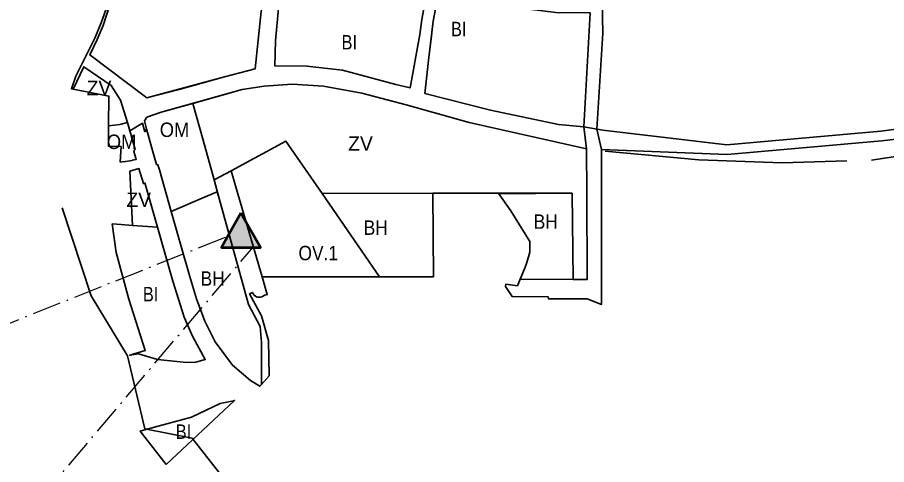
# Model space of a CAD drawing. Extents: x -650276 to -642489, y -1074311 to -1066658.
# Drawn here: x -645941 to -645218, y -1070271 to -1069899 of the extents above; entities that cross this region are included whole.
import ezdxf

# ---------------------------------------------------------------- set-up
doc = ezdxf.new("R2010")
doc.units = 0
doc.header["$LTSCALE"] = 4.8
doc.linetypes.add('DOT_DASHED', pattern=[7.7, 5, -1.2, 0.3, -1.2])
for name, color, linetype, lineweight in [('1', 7, 'Continuous', 35), ('11', 7, 'Continuous', 35), ('12', 7, 'Continuous', 35), ('15', 7, 'Continuous', 35), ('2', 7, 'Continuous', 35), ('40', 7, 'Continuous', 35), ('54', 7, 'Continuous', 35), ('55', 7, 'Continuous', 53)]:
    doc.layers.add(name, color=color, linetype=linetype, lineweight=lineweight)
doc.layers.add('62', color=7, linetype='Continuous')

msp = doc.modelspace()

# ---------------------------------------------------------------- hatches: boundary and pattern name
at = {"layer": '55'}
msp.add_hatch(color=256, dxfattribs=at).paths.add_polyline_path([(-645754.857, -1070061.969), (-645770.808, -1070090.615), (-645738.424, -1070090.615)])

# ---------------------------------------------------------------- linework, layer by layer
at = {"layer": '1'}
for points in [[(-645772.853, -1070049.868), (-645774.423, -1070044.167), (-645783.063, -1070047.855), (-645812.76, -1070060.53)], [(-645737.756, -1070204.389), (-645737.624, -1070169.544), (-645738.79, -1070156.281), (-645748.62, -1070137.889), (-645772.853, -1070049.868)], [(-645812.76, -1070060.53), (-645804.52, -1070089.63), (-645797.66, -1070113.88), (-645791.72, -1070133.09), (-645784.83, -1070151.9), (-645784.83, -1070151.9)], [(-645784.83, -1070151.9), (-645776.26, -1070168.94), (-645761.78, -1070188.29), (-645746.73, -1070201.04), (-645739.12, -1070205.9), (-645737.756, -1070204.389)]]:
    msp.add_lwpolyline(points, dxfattribs=at)
for points in [[(-645639.638, -1070114.895), (-645594.733, -1070114.868), (-645595.2, -1070045.403), (-645687.31, -1070045.724)], [(-645522.587, -1070116.952), (-645478.664, -1070117.114), (-645479.429, -1070045.409), (-645540.433, -1070045.752), (-645530.3, -1070060.08), (-645514.49, -1070085.4), (-645514.56, -1070090.91), (-645514.61, -1070094.35), (-645517.02, -1070103.08), (-645518.35, -1070106.87), (-645521.73, -1070114.83)]]:
    msp.add_lwpolyline(points, close=True, dxfattribs=at)
at = {"layer": '11'}
msp.add_lwpolyline([(-645639.638, -1070114.895), (-645687.31, -1070045.724), (-645717.36, -1070002.12), (-645762.868, -1070026.606), (-645757.215, -1070045.97), (-645737.075, -1070114.955)], close=True, dxfattribs=at)
at = {"layer": '12'}
for points in [[(-645794.679, -1069970.596), (-645821, -1069978), (-645833, -1069982), (-645835, -1069985), (-645833.32, -1069991.86)], [(-645777.143, -1070034.287), (-645786.238, -1070001.251), (-645794.679, -1069970.596)], [(-645833.32, -1069991.86), (-645828.9, -1070007.76), (-645825.08, -1070021.52)], [(-645825.08, -1070021.52), (-645823.76, -1070021.67), (-645822.549, -1070025.948), (-645812.76, -1070060.53), (-645783.063, -1070047.855), (-645774.423, -1070044.167), (-645777.143, -1070034.287)]]:
    msp.add_lwpolyline(points, dxfattribs=at)
msp.add_lwpolyline([(-645855.17, -1070019.44), (-645852.36, -1070019.01), (-645852.33, -1070019.2), (-645845.37, -1070018.12), (-645845.14, -1070018.08), (-645845.17, -1070017.91), (-645841.89, -1070017.42), (-645842.238, -1070016.251), (-645843.94, -1070010.6), (-645843, -1070009), (-645842.8, -1070008.59), (-645843.22, -1070007.12), (-645849.1, -1069986.42), (-645855.54, -1069988.24), (-645864.77, -1069989.26), (-645864.97, -1070006.16), (-645854.42, -1070006.47), (-645854.65, -1070010.44)], close=True, dxfattribs=at)
at = {"layer": '15'}
for points in [[(-645865.78, -1069888.76), (-645870.89, -1069903.5), (-645876.15, -1069916.47), (-645892.09, -1069947.98), (-645895.66, -1069958.42), (-645894.25, -1069958.7), (-645885.422, -1069940.184), (-645862.782, -1069955.809), (-645854.81, -1069967.927), (-645849.1, -1069986.42), (-645847.14, -1069993.34), (-645836.64, -1069987.18), (-645834.65, -1069994.21), (-645833.32, -1069991.86), (-645835, -1069985), (-645833, -1069982), (-645821, -1069978), (-645753.706, -1069959.071), (-645735.532, -1069956.306), (-645712.222, -1069954.725), (-645686.147, -1069956.306), (-645654.145, -1069962.232), (-645617.403, -1069971.714), (-645565.133, -1069986.508), (-645467.472, -1070008.38), (-645469.701, -1069990.011), (-645490.814, -1069988.074), (-645547.4, -1069976.382), (-645601.753, -1069962.317), (-645598.491, -1069932.472), (-645596.463, -1069914.335), (-645594.866, -1069902.242), (-645589.84, -1069875.892)], [(-645599.271, -1069873.685), (-645604.424, -1069900.701), (-645606.07, -1069913.163), (-645614.072, -1069957.797), (-645625.979, -1069954.92), (-645670.325, -1069943.002), (-645699.889, -1069939.714), (-645726.542, -1069939.398), (-645726.131, -1069918.457), (-645723.668, -1069891.356)], [(-645738.039, -1069894.231), (-645742.967, -1069941.862), (-645768.424, -1069948.431), (-645833, -1069966), (-645880.431, -1069930.3), (-645874.219, -1069917.496), (-645869.262, -1069905.935), (-645863.95, -1069889.468)], [(-645124.233, -1069980.695), (-645222.809, -1069993.701), (-645350.784, -1070005.227), (-645453.852, -1069992.968), (-645469.701, -1069990.011), (-645467.472, -1070008.38), (-645467.068, -1070044.959), (-645466.96, -1070117.157), (-645478.664, -1070117.114), (-645522.587, -1070116.952), (-645524.82, -1070122.48), (-645534.63, -1070121.09), (-645534.7, -1070122.95), (-645529.17, -1070131.4), (-645499.276, -1070131.652), (-645499.142, -1070133.293), (-645466.862, -1070133.219), (-645454.881, -1070137.836), (-645455.073, -1070009.111), (-645350.591, -1070013.242), (-645221.99, -1070001.66), (-645194.003, -1069998.417)], [(-645757.215, -1070045.97), (-645762.868, -1070026.606), (-645777.143, -1070034.287), (-645772.853, -1070049.868), (-645748.62, -1070137.889)], [(-645737.63, -1070147.39), (-645747.67, -1070129.14), (-645745.29, -1070127.83), (-645744.73, -1070129), (-645743.87, -1070130.15), (-645742.67, -1070131.07), (-645741.83, -1070131.53), (-645740.89, -1070131.8), (-645739.41, -1070131.93), (-645738.41, -1070131.78), (-645737.48, -1070131.45), (-645734.77, -1070130.18), (-645732.91, -1070129.5), (-645737.075, -1070114.955), (-645757.215, -1070045.97)], [(-645748.62, -1070137.889), (-645738.79, -1070156.281), (-645737.624, -1070169.544), (-645737.756, -1070204.389)], [(-645737.756, -1070204.389), (-645731.3, -1070197.24), (-645731.94, -1070167.87), (-645737.63, -1070147.39)]]:
    msp.add_lwpolyline(points, dxfattribs=at)
at = {"layer": '2'}
for points in [[(-645806, -1069959), (-645768.424, -1069948.431), (-645742.967, -1069941.862), (-645738.039, -1069894.231), (-645729.006, -1069844.136), (-645777.852, -1069832.241), (-645804.185, -1069825.84), (-645808.28, -1069865.39), (-645808.84, -1069870.75), (-645849.79, -1069868.4), (-645850.92, -1069863.41), (-645857.204, -1069862.954), (-645857.289, -1069863.338), (-645863.95, -1069889.468), (-645869.262, -1069905.935), (-645874.219, -1069917.496), (-645880.431, -1069930.3), (-645833, -1069966)], [(-645606.07, -1069913.163), (-645604.424, -1069900.701), (-645599.271, -1069873.685), (-645677.849, -1069855.3), (-645716.277, -1069847.01), (-645723.668, -1069891.356), (-645726.131, -1069918.457), (-645726.542, -1069939.398), (-645699.889, -1069939.714), (-645670.325, -1069943.002), (-645625.979, -1069954.92), (-645614.072, -1069957.797)], [(-645589.84, -1069875.892), (-645594.866, -1069902.242), (-645598.491, -1069932.472), (-645601.753, -1069962.317), (-645547.4, -1069976.382), (-645490.814, -1069988.074), (-645469.701, -1069990.011), (-645469.701, -1069990.011), (-645464.288, -1069895.362), (-645492.842, -1069895), (-645526.451, -1069890.745)], [(-645792.37, -1070186.01), (-645784.51, -1070183.77), (-645795.07, -1070164.26), (-645801.99, -1070148.51), (-645811.48, -1070118.65), (-645824.28, -1070073.67), (-645845.01, -1070072.12), (-645854.25, -1070071.4), (-645861.74, -1070070.95), (-645858.53, -1070094.64), (-645847.88, -1070133.4), (-645834.31, -1070176.15), (-645847.2, -1070180.14), (-645839.82, -1070178.94), (-645824.12, -1070183.63), (-645799.91, -1070186.32)], [(-645816.9, -1070270.96), (-645760.05, -1070217.79), (-645760.91, -1070217.98), (-645772.08, -1070220.39), (-645795.85, -1070231.81), (-645833.92, -1070241.96), (-645838.53, -1070243.19)]]:
    msp.add_lwpolyline(points, close=True, dxfattribs=at)
at = {"layer": '40'}
for points in [[(-645849.1, -1069986.42), (-645854.81, -1069967.927), (-645862.782, -1069955.809), (-645885.422, -1069940.184), (-645894.25, -1069958.7), (-645864.48, -1069964.53), (-645864.77, -1069989.26), (-645855.54, -1069988.24)], [(-645595.2, -1070045.403), (-645479.429, -1070045.409), (-645478.664, -1070117.114), (-645466.96, -1070117.157), (-645467.068, -1070044.959), (-645467.472, -1070008.38), (-645565.133, -1069986.508), (-645617.403, -1069971.714), (-645654.145, -1069962.232), (-645686.147, -1069956.306), (-645712.222, -1069954.725), (-645735.532, -1069956.306), (-645753.706, -1069959.071), (-645794.679, -1069970.596), (-645786.238, -1070001.251), (-645777.143, -1070034.287), (-645762.868, -1070026.606), (-645717.36, -1070002.12), (-645687.31, -1070045.724)], [(-645834.8, -1070036.71), (-645835.91, -1070037.31), (-645839.64, -1070024.9), (-645847.08, -1070027.09), (-645845.01, -1070072.12), (-645824.28, -1070073.67), (-645824.28, -1070073.67)]]:
    msp.add_lwpolyline(points, close=True, dxfattribs=at)
at = {"layer": '54'}
for points in [[(-645624.473, -1069340.207), (-645597.606, -1069359.137), (-645542.894, -1069403.796), (-645505.738, -1069437.197), (-645484.202, -1069466.216), (-645467.655, -1069503.794), (-645460.072, -1069535.704), (-645458, -1069561.601), (-645458, -1069658.925), (-645456, -1069668), (-645455.002, -1069859.825), (-645453.95, -1069912.05), (-645458.804, -1069992.044), (-645455.073, -1070009.111)], [(-645230.538, -1070017.864), (-644946.741, -1069974.541), (-644816.387, -1069962.572), (-644667.646, -1069930.034), (-644586.303, -1069905.244), (-644248.286, -1069794.155), (-644097.378, -1069760.147), (-643995.653, -1069721.915)], [(-645451.854, -1070010.265), (-645374.117, -1070017.569), (-645304.693, -1070020.185), (-645251.015, -1070018.538)], [(-645903.547, -1070057.381), (-645879.191, -1070130.665), (-645848.973, -1070180.543), (-645834.684, -1070241.324), (-645795.429, -1070249.201), (-645711.259, -1070356.569)]]:
    msp.add_lwpolyline(points, dxfattribs=at)
at = {"layer": '55', "linetype": 'DOT_DASHED', "lineweight": 25}
for p, q in [((-647060.176, -1070597.455), (-645765.418, -1070080.935)), ((-646590, -1071090), (-645744.292, -1070089.84))]:
    msp.add_line(p, q, dxfattribs=at)
at = {"layer": '55'}
msp.add_lwpolyline([(-645754.857, -1070061.969), (-645770.808, -1070090.615), (-645738.424, -1070090.615)], close=True, dxfattribs=at)

# ---------------------------------------------------------------- texts
at = {"layer": '62'}
for s, width, p in [('BI', 0.85, (-645580.138, -1069914.734)), ('BI', 0.85, (-645671.138, -1069925.734)), ('OM', 0.95, (-645822.28, -1069998.561)), ('OM', 0.95, (-645866.28, -1070008.561)), ('BH', 0.9, (-645511.328, -1070074.977)), ('BH', 0.9, (-645652.699, -1070079.977)), ('OV.1', 0.9, (-645706.926, -1070101.134)), ('BH', 0.9, (-645788.337, -1070122.32)), ('BI', 0.85, (-645836.337, -1070135.32)), ('BI', 0.85, (-645808.987, -1070249.726))]:
    msp.add_text(s, height=12, dxfattribs=dict(at, width=width)).set_placement(p)
for p in [(-645883.022, -1069963.776), (-645665.601, -1070009.978), (-645850.022, -1070056.776)]:
    msp.add_text('ZV', height=12, dxfattribs=at).set_placement(p)

doc.saveas('drawing.dxf')
